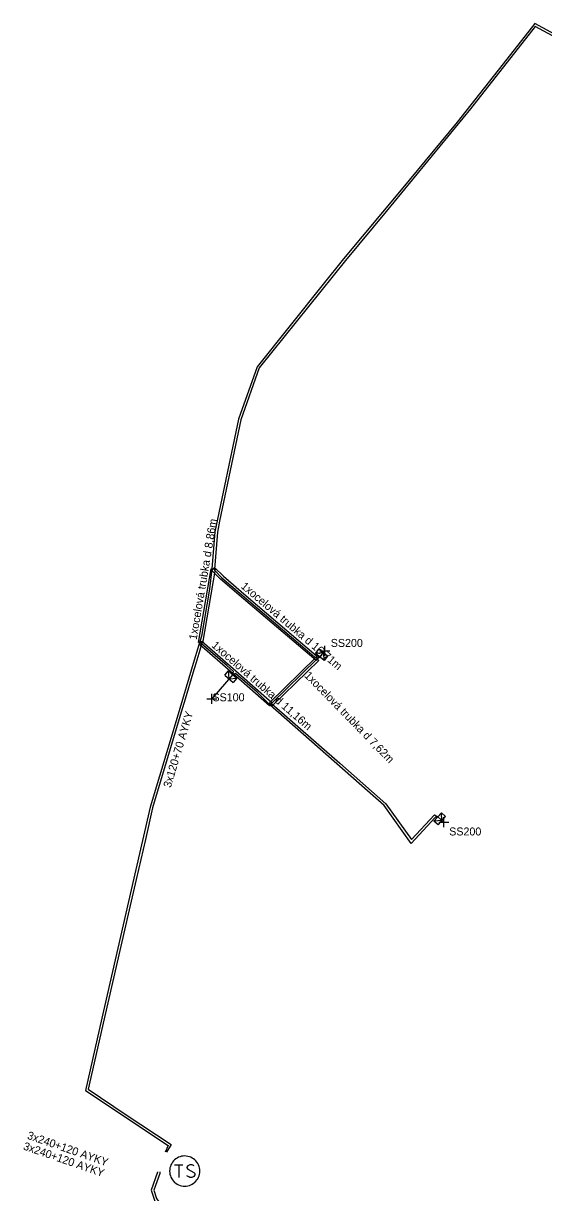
# Model space of a CAD drawing. Extents: x -737417 to -734469, y -1145580 to -1142703.
# Drawn here: x -736642.6 to -736577.5, y -1144288.6 to -1144142.5 of the extents above; entities that cross this region are included whole.
import ezdxf

# ---------------------------------------------------------------- set-up
doc = ezdxf.new("R2010")
doc.units = 0
for name, color, linetype in [('Vrstva 1', 7, 'Continuous'), ('Vrstva 20', 7, 'Continuous'), ('Vrstva 21', 7, 'Continuous'), ('Vrstva 25', 7, 'Continuous'), ('Vrstva 31', 7, 'Continuous'), ('Vrstva 33', 7, 'Continuous'), ('Vrstva 34', 7, 'Continuous'), ('Vrstva 5', 7, 'Continuous'), ('Vrstva 59', 7, 'Continuous'), ('Vrstva 6', 7, 'Continuous'), ('Vrstva 9', 7, 'Continuous')]:
    doc.layers.add(name, color=color, linetype=linetype)

# ---------------------------------------------------------------- blocks, each defined once
blk = doc.blocks.new('NN800')
at = {"layer": 'Vrstva 1'}
for points in [[(-0.44, 0.44), (0.44, -0.44)], [(-0.44, -0.44), (0.44, 0.44)]]:
    blk.add_lwpolyline(points, dxfattribs=at)
blk = doc.blocks.new('NN630')
at = {"layer": 'Vrstva 9'}
for points in [[(0, -0.7), (-0.7, 0)], [(-0.7, -0.7), (-0.7, 0), (0.7, 0), (0.7, -0.7)], [(-0.7, -0.7), (0.7, -0.7)], [(0, -0.7), (0.7, 0)]]:
    blk.add_lwpolyline(points, dxfattribs=at)
blk = doc.blocks.new('NN610')
at = {"layer": 'Vrstva 6'}
for points in [[(1.88, 0), (1.87, 0.2), (1.84, 0.39), (1.79, 0.58), (1.72, 0.77), (1.63, 0.94), (1.52, 1.11), (1.4, 1.26), (1.26, 1.4), (1.1, 1.53), (0.94, 1.63), (0.76, 1.72), (0.58, 1.8), (0.19, 1.88), (0.19, 1.88), (-0.01, 1.89), (-0.21, 1.88), (-0.4, 1.85), (-0.59, 1.8), (-0.78, 1.72), (-0.95, 1.63), (-1.12, 1.53), (-1.27, 1.4), (-1.41, 1.26), (-1.54, 1.11), (-1.64, 0.94), (-1.73, 0.77), (-1.8, 0.58), (-1.86, 0.39), (-1.89, 0.2), (-1.9, 0), (-1.89, -0.2), (-1.86, -0.39), (-1.8, -0.58), (-1.73, -0.77), (-1.64, -0.95), (-1.54, -1.11), (-1.41, -1.27), (-1.27, -1.41), (-1.12, -1.53), (-0.95, -1.64), (-0.78, -1.73), (-0.59, -1.8), (-0.4, -1.85), (-0.21, -1.88), (-0.01, -1.89), (0.19, -1.88), (0.39, -1.85), (0.58, -1.8), (0.76, -1.73), (0.94, -1.64), (1.1, -1.53), (1.26, -1.41), (1.4, -1.27), (1.52, -1.11), (1.63, -0.95), (1.72, -0.77), (1.79, -0.58), (1.84, -0.39), (1.87, -0.2), (1.88, 0)], [(-1.27, 0.78), (-0.26, 0.78)], [(-0.76, 0.78), (-0.76, -0.79)], [(1.19, 0.66), (0.94, 0.78), (0.62, 0.78), (0.37, 0.66), (0.24, 0.47), (0.24, 0.4), (0.37, 0.22), (1.12, -0.16), (1.25, -0.32), (1.25, -0.48), (1.12, -0.67), (0.87, -0.79), (0.62, -0.79), (0.49, -0.73), (0.24, -0.6)]]:
    blk.add_lwpolyline(points, dxfattribs=at)

msp = doc.modelspace()

# ---------------------------------------------------------------- linework, layer by layer
at = {"layer": 'Vrstva 20'}
for points in [[(-736618.58, -1144210.75), (-736620.15, -1144219.98), (-736620.65, -1144219.9), (-736619.08, -1144210.67)], [(-736619.01, -1144210.89), (-736618.65, -1144210.53), (-736617.56, -1144211.62), (-736614.71, -1144214.05), (-736605.65, -1144221.76), (-736605.97, -1144222.14), (-736615.03, -1144214.43), (-736617.9, -1144211.99)], [(-736620.56, -1144220.13), (-736620.23, -1144219.75), (-736616.01, -1144223.44), (-736611.45, -1144227.43), (-736611.79, -1144227.81), (-736616.33, -1144223.82)], [(-736605.64, -1144222.13), (-736611.45, -1144227.8), (-736611.79, -1144227.44), (-736605.98, -1144221.77)]]:
    msp.add_lwpolyline(points, close=True, dxfattribs=at)
at = {"layer": 'Vrstva 5'}
for points in [[(-736570.62, -1144146.88), (-736578.62, -1144142.53), (-736582.12, -1144147), (-736588.34, -1144154.86), (-736595.34, -1144163.33), (-736602.52, -1144171.97), (-736605.09, -1144175.11), (-736613.34, -1144185.43), (-736615.66, -1144191.97), (-736618.61, -1144206.06), (-736618.98, -1144210.7), (-736619.28, -1144213.24), (-736620.29, -1144219.12), (-736621.19, -1144222.12), (-736623.33, -1144229.27), (-736626.7, -1144240.49), (-736628.74, -1144249.35), (-736632.76, -1144266.85), (-736634.8, -1144275.87), (-736624.44, -1144282.75), (-736624.83, -1144283.58)], [(-736567.49, -1144148.88), (-736578.58, -1144142.91), (-736586.64, -1144153.21), (-736597.19, -1144166.05), (-736602.28, -1144172.16), (-736613.08, -1144185.57), (-736615.36, -1144192.05), (-736618.03, -1144204.74), (-736618.31, -1144206.1), (-736618.68, -1144210.72), (-736618.68, -1144210.87), (-736617.74, -1144211.8), (-736607.92, -1144220.18), (-736606.15, -1144221.67), (-736605.51, -1144221.72), (-736605.81, -1144221.95), (-736611.52, -1144227.51), (-736603.01, -1144234.98), (-736597.23, -1144240.07), (-736594.05, -1144244.52), (-736591.18, -1144241.45), (-736590.76, -1144241.69), (-736591.08, -1144241.78), (-736594.08, -1144245), (-736597.45, -1144240.27), (-736611.72, -1144227.73), (-736613.35, -1144226.1), (-736616.03, -1144223.75), (-736616.39, -1144223.9), (-736616.3, -1144223.53), (-736617.14, -1144222.78), (-736620.28, -1144220.05), (-736620.51, -1144220.85), (-736621.01, -1144222.5), (-736621.37, -1144223.71), (-736622.34, -1144226.97), (-736622.83, -1144228.6), (-736626.41, -1144240.57), (-736627.31, -1144244.53), (-736628.46, -1144249.53), (-736629.34, -1144253.31), (-736632.46, -1144266.91), (-736634.46, -1144275.73), (-736629.69, -1144278.91), (-736624.07, -1144282.63), (-736624.66, -1144283.59)], [(-736625.8, -1144286.04), (-736625.81, -1144286.07), (-736626.57, -1144288.33), (-736626.06, -1144289.96), (-736625.58, -1144289.92)], [(-736625.49, -1144286.03), (-736625.51, -1144286.27), (-736626.25, -1144288.33), (-736625.93, -1144289.37), (-736625.63, -1144289.8)]]:
    msp.add_lwpolyline(points, dxfattribs=at)
at = {"layer": 'Vrstva 59'}
for points in [[(-736605.51, -1144221.72), (-736604.88, -1144220.94)], [(-736616.39, -1144223.9), (-736618.99, -1144226.94)], [(-736590.76, -1144241.69), (-736590.01, -1144242.35)]]:
    msp.add_lwpolyline(points, dxfattribs=at)

# ---------------------------------------------------------------- block references
at = {"layer": 'Vrstva 25'}
msp.add_blockref('NN610', (-736622.38, -1144285.95), dxfattribs=at)
at = {"layer": 'Vrstva 31'}
for p, rotation in [((-736605.51, -1144221.72), 140.90890828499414), ((-736616.39, -1144223.9), -40.54538050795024), ((-736590.76, -1144241.69), 48.67576944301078)]:
    msp.add_blockref('NN630', p, dxfattribs=dict(at, rotation=rotation))
at = {"layer": 'Vrstva 34'}
for p, rotation in [((-736604.88, -1144220.94), 44.99999995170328), ((-736618.99, -1144226.94), 45.00000009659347), ((-736590.01, -1144242.35), 45)]:
    msp.add_blockref('NN800', p, dxfattribs=dict(at, rotation=rotation))

# ---------------------------------------------------------------- texts
at = {"layer": 'Vrstva 21'}
for s, rotation, p in [('1xocelová trubka d 8,86m', 80.347, (-736620.9, -1144219.62)), ('1xocelová trubka d 16,71m', 319.609, (-736615.45, -1144213)), ('1xocelová trubka d 11,16m', 318.893, (-736619.11, -1144220.37)), ('1xocelová trubka d 7,62m', 314.301, (-736607.5, -1144224.1))]:
    msp.add_text(s, height=1, rotation=rotation, dxfattribs=at).set_placement(p)
at = {"layer": 'Vrstva 33'}
for s, p in [('SS200', (-736604.13, -1144220.45)), ('SS100', (-736618.92, -1144227.24)), ('SS200', (-736589.32, -1144244.01))]:
    msp.add_text(s, height=1, dxfattribs=at).set_placement(p)
at = {"layer": 'Vrstva 6'}
for s, rotation, p in [('3x120+70 AYKY', 73.368, (-736624.14, -1144238.12)), ('3x240+120 AYKY', 340.832, (-736642.17, -1144281.89)), ('3x240+120 AYKY', 340.842, (-736642.66, -1144283.23))]:
    msp.add_text(s, height=1, rotation=rotation, dxfattribs=at).set_placement(p)

doc.saveas('drawing.dxf')
